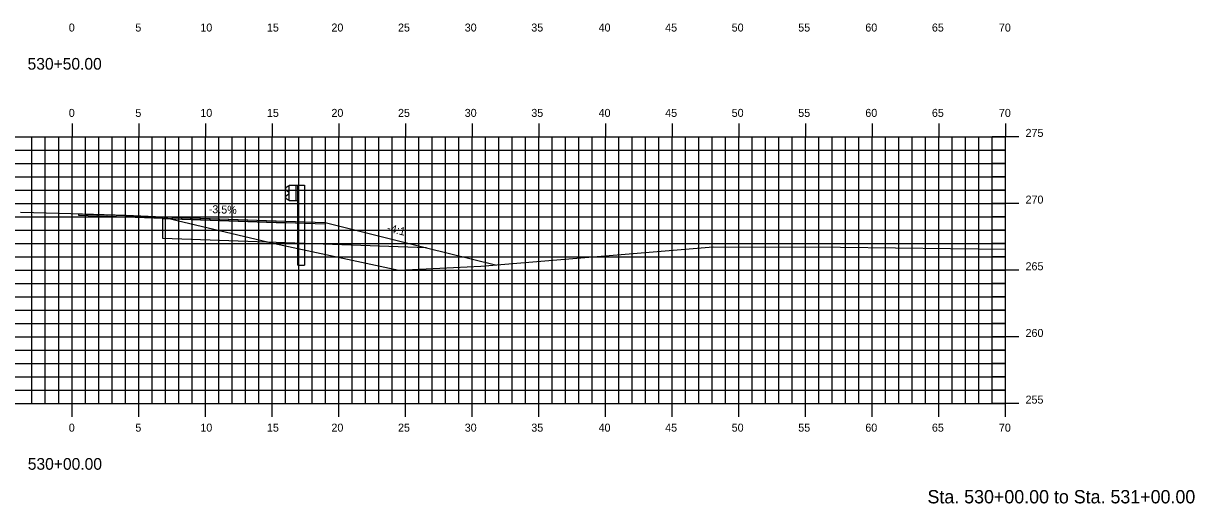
# Model space of a CAD drawing. Extents: x 1170543 to 1177585, y 609599 to 610623.
# Drawn here: x 1176610.3 to 1176698.1, y 610270.3 to 610306.3 of the extents above; entities that cross this region are included whole.
import ezdxf

# ---------------------------------------------------------------- set-up
doc = ezdxf.new("R2010")
doc.units = 0
for name, color, linetype in [('ANNOTATION', 7, 'Continuous'), ('D_Guardrail_Beam_Rt', 7, 'Continuous'), ('D_Roadway_Centerline', 7, 'Continuous'), ('D_Roadway_Edge_TW', 7, 'Continuous'), ('D_Roadway_SubGrade', 7, 'Continuous'), ('H_V ANNOTATION', 7, 'Continuous'), ('MAJOR', 7, 'Continuous'), ('MINOR', 7, 'Continuous'), ('S_Roadway_Centerline', 7, 'Continuous')]:
    doc.layers.add(name, color=color, linetype=linetype)

msp = doc.modelspace()

# ---------------------------------------------------------------- linework, layer by layer
at = {"layer": 'D_Guardrail_Beam_Rt'}
for p, q in [((1176630.169, 610294.093), (1176630.095, 610294.079)), ((1176630.169, 610294.177), (1176630.856, 610294.177)), ((1176630.169, 610293.01), (1176630.169, 610294.177)), ((1176630.69, 610294.177), (1176630.69, 610293.01)), ((1176630.794, 610294.177), (1176630.794, 610293.01)), ((1176630.856, 610294.177), (1176631.327, 610294.177)), ((1176630.856, 610294.177), (1176630.856, 610293.01)), ((1176631.327, 610294.177), (1176631.327, 610288.177)), ((1176630.079, 610294.072), (1176629.935, 610293.972)), ((1176629.935, 610293.829), (1176630.131, 610293.693)), ((1176630.131, 610293.494), (1176629.935, 610293.358)), ((1176629.935, 610293.215), (1176630.079, 610293.115)), ((1176630.164, 610293.629), (1176630.164, 610293.558)), ((1176630.095, 610293.108), (1176630.169, 610293.093)), ((1176630.856, 610293.01), (1176630.169, 610293.01)), ((1176630.835, 610288.177), (1176630.835, 610293.01)), ((1176630.835, 610288.177), (1176631.327, 610288.177))]:
    msp.add_line(p, q, dxfattribs=at)
for centre, major_axis, start_param, end_param in [((1176629.986, 610293.901), (-0.0877, 0), 5.323254, 7.243116), ((1176629.986, 610293.286), (-0.0877, 0), 5.323254, 7.243116), ((1176630.103, 610294.038), (-0.0417, 0), 4.907132, 5.323254), ((1176630.085, 610293.629), (0.0789, 0), 0, 0.959931), ((1176630.085, 610293.558), (0.0789, 0), 5.323254, 6.283185), ((1176630.103, 610293.149), (-0.0417, 0), 0.959931, 1.376053)]:
    msp.add_ellipse(centre, major_axis=major_axis, ratio=0.995501, start_param=start_param, end_param=end_param, dxfattribs=at)
at = {"layer": 'D_Roadway_Centerline'}
msp.add_lwpolyline([(1176614.421, 610292.031), (1176614.882, 610292.016), (1176618.331, 610291.896), (1176620.131, 610291.834), (1176620.705, 610291.813), (1176622.762, 610291.741), (1176629.898, 610291.491), (1176632.89, 610291.386), (1176632.89, 610291.386), (1176640.471, 610289.491), (1176640.471, 610289.491), (1176640.471, 610289.491), (1176640.471, 610289.491), (1176640.471, 610289.491), (1176645.646, 610288.197)], dxfattribs=at)
at = {"layer": 'D_Roadway_Edge_TW'}
msp.add_lwpolyline([(1176614.421, 610292.031), (1176620.705, 610291.813), (1176629.898, 610291.491), (1176629.898, 610291.366), (1176614.421, 610291.906), (1176614.421, 610292.031)], dxfattribs=at)
msp.add_lwpolyline([(1176614.421, 610292.031), (1176620.705, 610291.813), (1176629.898, 610291.491), (1176629.898, 610291.366), (1176614.421, 610291.906), (1176614.421, 610292.031)], dxfattribs=at)
msp.add_lwpolyline([(1176614.421, 610292.031), (1176620.705, 610291.813), (1176629.898, 610291.491), (1176632.89, 610291.386), (1176632.89, 610291.262), (1176629.898, 610291.366), (1176614.421, 610291.906)], close=True, dxfattribs=at)
at = {"layer": 'D_Roadway_SubGrade'}
msp.add_lwpolyline([(1176629.898, 610291.491), (1176632.89, 610291.386), (1176640.471, 610289.491), (1176629.898, 610289.866), (1176620.705, 610290.188), (1176620.705, 610291.688), (1176629.898, 610291.366)], close=True, dxfattribs=at)
at = {"layer": 'MAJOR'}
for p, q in [((1176613.898, 610298.803), (1176613.898, 610297.801)), ((1176618.898, 610298.803), (1176618.898, 610297.801)), ((1176623.898, 610298.803), (1176623.898, 610297.801)), ((1176628.898, 610298.803), (1176628.898, 610297.801)), ((1176633.898, 610298.803), (1176633.898, 610297.801)), ((1176638.898, 610298.803), (1176638.898, 610297.801)), ((1176643.898, 610298.803), (1176643.898, 610297.801)), ((1176648.898, 610298.803), (1176648.898, 610297.801)), ((1176653.898, 610298.803), (1176653.898, 610297.801)), ((1176658.898, 610298.803), (1176658.898, 610297.801)), ((1176663.898, 610298.803), (1176663.898, 610297.801)), ((1176668.898, 610298.803), (1176668.898, 610297.801)), ((1176673.898, 610298.803), (1176673.898, 610297.801)), ((1176678.898, 610298.803), (1176678.898, 610297.801)), ((1176683.898, 610298.803), (1176683.898, 610297.801)), ((1176543.898, 610297.801), (1176683.898, 610297.801)), ((1176543.898, 610297.801), (1176683.898, 610297.801)), ((1176613.898, 610277.801), (1176613.898, 610297.801)), ((1176618.898, 610277.801), (1176618.898, 610297.801)), ((1176623.898, 610277.801), (1176623.898, 610297.801)), ((1176628.898, 610277.801), (1176628.898, 610297.801)), ((1176633.898, 610277.801), (1176633.898, 610297.801)), ((1176638.898, 610277.801), (1176638.898, 610297.801)), ((1176643.898, 610277.801), (1176643.898, 610297.801)), ((1176648.898, 610277.801), (1176648.898, 610297.801)), ((1176653.898, 610277.801), (1176653.898, 610297.801)), ((1176658.898, 610277.801), (1176658.898, 610297.801)), ((1176663.898, 610277.801), (1176663.898, 610297.801)), ((1176668.898, 610277.801), (1176668.898, 610297.801)), ((1176673.898, 610277.801), (1176673.898, 610297.801)), ((1176678.898, 610277.801), (1176678.898, 610297.801)), ((1176684.9, 610297.801), (1176682.896, 610297.801)), ((1176683.898, 610277.801), (1176683.898, 610297.801)), ((1176683.898, 610277.801), (1176683.898, 610297.801)), ((1176543.898, 610292.801), (1176683.898, 610292.801)), ((1176684.9, 610292.801), (1176682.896, 610292.801)), ((1176543.898, 610287.801), (1176683.898, 610287.801)), ((1176684.9, 610287.801), (1176682.896, 610287.801)), ((1176543.898, 610282.801), (1176683.898, 610282.801)), ((1176684.9, 610282.801), (1176682.896, 610282.801)), ((1176543.898, 610277.801), (1176683.898, 610277.801)), ((1176543.898, 610277.801), (1176683.898, 610277.801)), ((1176613.898, 610276.799), (1176613.898, 610277.801)), ((1176618.898, 610276.799), (1176618.898, 610277.801)), ((1176623.898, 610276.799), (1176623.898, 610277.801)), ((1176628.898, 610276.799), (1176628.898, 610277.801)), ((1176633.898, 610276.799), (1176633.898, 610277.801)), ((1176638.898, 610276.799), (1176638.898, 610277.801)), ((1176643.898, 610276.799), (1176643.898, 610277.801)), ((1176648.898, 610276.799), (1176648.898, 610277.801)), ((1176653.898, 610276.799), (1176653.898, 610277.801)), ((1176658.898, 610276.799), (1176658.898, 610277.801)), ((1176663.898, 610276.799), (1176663.898, 610277.801)), ((1176668.898, 610276.799), (1176668.898, 610277.801)), ((1176673.898, 610276.799), (1176673.898, 610277.801)), ((1176678.898, 610276.799), (1176678.898, 610277.801)), ((1176684.9, 610277.801), (1176682.896, 610277.801)), ((1176683.898, 610276.799), (1176683.898, 610277.801))]:
    msp.add_line(p, q, dxfattribs=at)
at = {"layer": 'MINOR'}
for p, q in [((1176610.898, 610277.801), (1176610.898, 610297.801)), ((1176611.898, 610277.801), (1176611.898, 610297.801)), ((1176612.898, 610277.801), (1176612.898, 610297.801)), ((1176614.898, 610277.801), (1176614.898, 610297.801)), ((1176615.898, 610277.801), (1176615.898, 610297.801)), ((1176616.898, 610277.801), (1176616.898, 610297.801)), ((1176617.898, 610277.801), (1176617.898, 610297.801)), ((1176619.898, 610277.801), (1176619.898, 610297.801)), ((1176620.898, 610277.801), (1176620.898, 610297.801)), ((1176621.898, 610277.801), (1176621.898, 610297.801)), ((1176622.898, 610277.801), (1176622.898, 610297.801)), ((1176624.898, 610277.801), (1176624.898, 610297.801)), ((1176625.898, 610277.801), (1176625.898, 610297.801)), ((1176626.898, 610277.801), (1176626.898, 610297.801)), ((1176627.898, 610277.801), (1176627.898, 610297.801)), ((1176629.898, 610277.801), (1176629.898, 610297.801)), ((1176630.898, 610277.801), (1176630.898, 610297.801)), ((1176631.898, 610277.801), (1176631.898, 610297.801)), ((1176632.898, 610277.801), (1176632.898, 610297.801)), ((1176634.898, 610277.801), (1176634.898, 610297.801)), ((1176635.898, 610277.801), (1176635.898, 610297.801)), ((1176636.898, 610277.801), (1176636.898, 610297.801)), ((1176637.898, 610277.801), (1176637.898, 610297.801)), ((1176639.898, 610277.801), (1176639.898, 610297.801)), ((1176640.898, 610277.801), (1176640.898, 610297.801)), ((1176641.898, 610277.801), (1176641.898, 610297.801)), ((1176642.898, 610277.801), (1176642.898, 610297.801)), ((1176644.898, 610277.801), (1176644.898, 610297.801)), ((1176645.898, 610277.801), (1176645.898, 610297.801)), ((1176646.898, 610277.801), (1176646.898, 610297.801)), ((1176647.898, 610277.801), (1176647.898, 610297.801)), ((1176649.898, 610277.801), (1176649.898, 610297.801)), ((1176650.898, 610277.801), (1176650.898, 610297.801)), ((1176651.898, 610277.801), (1176651.898, 610297.801)), ((1176652.898, 610277.801), (1176652.898, 610297.801)), ((1176654.898, 610277.801), (1176654.898, 610297.801)), ((1176655.898, 610277.801), (1176655.898, 610297.801)), ((1176656.898, 610277.801), (1176656.898, 610297.801)), ((1176657.898, 610277.801), (1176657.898, 610297.801)), ((1176659.898, 610277.801), (1176659.898, 610297.801)), ((1176660.898, 610277.801), (1176660.898, 610297.801)), ((1176661.898, 610277.801), (1176661.898, 610297.801)), ((1176662.898, 610277.801), (1176662.898, 610297.801)), ((1176664.898, 610277.801), (1176664.898, 610297.801)), ((1176665.898, 610277.801), (1176665.898, 610297.801)), ((1176666.898, 610277.801), (1176666.898, 610297.801)), ((1176667.898, 610277.801), (1176667.898, 610297.801)), ((1176669.898, 610277.801), (1176669.898, 610297.801)), ((1176670.898, 610277.801), (1176670.898, 610297.801)), ((1176671.898, 610277.801), (1176671.898, 610297.801)), ((1176672.898, 610277.801), (1176672.898, 610297.801)), ((1176674.898, 610277.801), (1176674.898, 610297.801)), ((1176675.898, 610277.801), (1176675.898, 610297.801)), ((1176676.898, 610277.801), (1176676.898, 610297.801)), ((1176677.898, 610277.801), (1176677.898, 610297.801)), ((1176679.898, 610277.801), (1176679.898, 610297.801)), ((1176680.898, 610277.801), (1176680.898, 610297.801)), ((1176681.898, 610277.801), (1176681.898, 610297.801)), ((1176682.898, 610277.801), (1176682.898, 610297.801)), ((1176543.898, 610296.801), (1176683.898, 610296.801)), ((1176683.898, 610296.801), (1176682.896, 610296.801)), ((1176543.898, 610295.801), (1176683.898, 610295.801)), ((1176683.898, 610295.801), (1176682.896, 610295.801)), ((1176543.898, 610294.801), (1176683.898, 610294.801)), ((1176683.898, 610294.801), (1176682.896, 610294.801)), ((1176543.898, 610293.801), (1176683.898, 610293.801)), ((1176683.898, 610293.801), (1176682.896, 610293.801)), ((1176543.898, 610291.801), (1176683.898, 610291.801)), ((1176683.898, 610291.801), (1176682.896, 610291.801)), ((1176543.898, 610290.801), (1176683.898, 610290.801)), ((1176683.898, 610290.801), (1176682.896, 610290.801)), ((1176543.898, 610289.801), (1176683.898, 610289.801)), ((1176683.898, 610289.801), (1176682.896, 610289.801)), ((1176543.898, 610288.801), (1176683.898, 610288.801)), ((1176683.898, 610288.801), (1176682.896, 610288.801)), ((1176543.898, 610286.801), (1176683.898, 610286.801)), ((1176683.898, 610286.801), (1176682.896, 610286.801)), ((1176543.898, 610285.801), (1176683.898, 610285.801)), ((1176683.898, 610285.801), (1176682.896, 610285.801)), ((1176543.898, 610284.801), (1176683.898, 610284.801)), ((1176683.898, 610284.801), (1176682.896, 610284.801)), ((1176543.898, 610283.801), (1176683.898, 610283.801)), ((1176683.898, 610283.801), (1176682.896, 610283.801)), ((1176543.898, 610281.801), (1176683.898, 610281.801)), ((1176683.898, 610281.801), (1176682.896, 610281.801)), ((1176543.898, 610280.801), (1176683.898, 610280.801)), ((1176683.898, 610280.801), (1176682.896, 610280.801)), ((1176543.898, 610279.801), (1176683.898, 610279.801)), ((1176683.898, 610279.801), (1176682.896, 610279.801)), ((1176543.898, 610278.801), (1176683.898, 610278.801)), ((1176683.898, 610278.801), (1176682.896, 610278.801))]:
    msp.add_line(p, q, dxfattribs=at)
at = {"layer": 'S_Roadway_Centerline'}
msp.add_lwpolyline([(1176610.032, 610292.148), (1176612.941, 610292.075), (1176614.694, 610292.023), (1176617.956, 610291.93), (1176618.515, 610291.909), (1176620.705, 610291.813), (1176620.884, 610291.753), (1176621.786, 610291.523), (1176629.076, 610289.807), (1176638.403, 610287.811), (1176644.554, 610288.107), (1176661.985, 610289.549), (1176671.52, 610289.53), (1176683.898, 610289.379)], dxfattribs=at)

# ---------------------------------------------------------------- texts
at = {"layer": 'ANNOTATION'}
for s, rotation, p in [('-3.5%', 357.99295, (1176624.144, 610292.093)), ('-4:1', 345.96376, (1176637.472, 610290.719))]:
    msp.add_text(s, height=0.6, rotation=rotation, dxfattribs=at).set_placement(p)
at = {"layer": 'H_V ANNOTATION'}
for s, height, p in [('0', 0.6, (1176613.657, 610305.701)), ('5', 0.6, (1176618.649, 610305.701)), ('10', 0.6, (1176623.523, 610305.701)), ('15', 0.6, (1176628.515, 610305.701)), ('20', 0.6, (1176633.352, 610305.701)), ('25', 0.6, (1176638.344, 610305.701)), ('30', 0.6, (1176643.347, 610305.701)), ('35', 0.6, (1176648.339, 610305.701)), ('40', 0.6, (1176653.384, 610305.701)), ('45', 0.6, (1176658.376, 610305.701)), ('50', 0.6, (1176663.363, 610305.701)), ('55', 0.6, (1176668.355, 610305.701)), ('60', 0.6, (1176673.384, 610305.701)), ('65', 0.6, (1176678.376, 610305.701)), ('70', 0.6, (1176683.4, 610305.701)), ('530+50.00', 0.875, (1176610.566, 610302.844)), ('0', 0.6, (1176613.657, 610299.301)), ('5', 0.6, (1176618.649, 610299.301)), ('10', 0.6, (1176623.523, 610299.301)), ('15', 0.6, (1176628.515, 610299.301)), ('20', 0.6, (1176633.352, 610299.301)), ('25', 0.6, (1176638.344, 610299.301)), ('30', 0.6, (1176643.347, 610299.301)), ('35', 0.6, (1176648.339, 610299.301)), ('40', 0.6, (1176653.384, 610299.301)), ('45', 0.6, (1176658.376, 610299.301)), ('50', 0.6, (1176663.363, 610299.301)), ('55', 0.6, (1176668.355, 610299.301)), ('60', 0.6, (1176673.384, 610299.301)), ('65', 0.6, (1176678.376, 610299.301)), ('70', 0.6, (1176683.4, 610299.301)), ('275', 0.6, (1176685.398, 610297.801)), ('270', 0.6, (1176685.398, 610292.801)), ('265', 0.6, (1176685.398, 610287.801)), ('260', 0.6, (1176685.398, 610282.801)), ('255', 0.6, (1176685.398, 610277.801)), ('0', 0.6, (1176613.657, 610275.701)), ('5', 0.6, (1176618.649, 610275.701)), ('10', 0.6, (1176623.523, 610275.701)), ('15', 0.6, (1176628.515, 610275.701)), ('20', 0.6, (1176633.352, 610275.701)), ('25', 0.6, (1176638.344, 610275.701)), ('30', 0.6, (1176643.347, 610275.701)), ('35', 0.6, (1176648.339, 610275.701)), ('40', 0.6, (1176653.384, 610275.701)), ('45', 0.6, (1176658.376, 610275.701)), ('50', 0.6, (1176663.363, 610275.701)), ('55', 0.6, (1176668.355, 610275.701)), ('60', 0.6, (1176673.384, 610275.701)), ('65', 0.6, (1176678.376, 610275.701)), ('70', 0.6, (1176683.4, 610275.701)), ('530+00.00', 0.875, (1176610.582, 610272.844)), ('Sta. 530+00.00 to Sta. 531+00.00', 1.0002, (1176678.044, 610270.321))]:
    msp.add_text(s, height=height, dxfattribs=at).set_placement(p)

doc.saveas('drawing.dxf')
